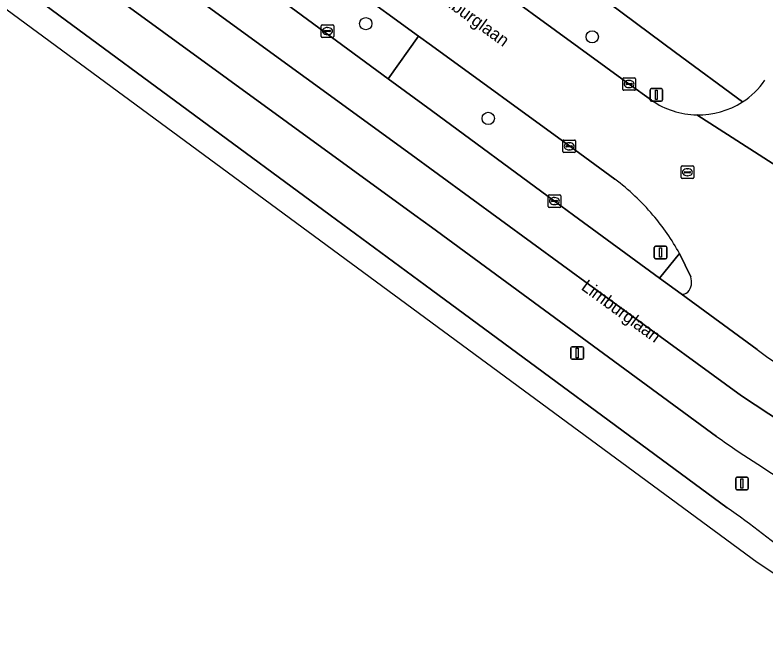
# Model space of a CAD drawing. Extents: x 159674 to 160531, y 382172 to 382904.
# Drawn here: x 159966.8 to 160026.6, y 382215.3 to 382265.9 of the extents above; entities that cross this region are included whole.
import ezdxf

# ---------------------------------------------------------------- set-up
doc = ezdxf.new("R2010")
doc.units = 0
for name, color, linetype in [('IMGEO_Berm_groen', 7, 'Continuous'), ('IMGEO_Boom', 7, 'Continuous'), ('IMGEO_Erf', 7, 'Continuous'), ('IMGEO_Kolk', 7, 'Continuous'), ('IMGEO_Lichtmast', 7, 'Continuous'), ('IMGEO_Openbare_ruimte_label', 7, 'Continuous'), ('IMGEO_Rijbaan_lokaal_open', 7, 'Continuous'), ('IMGEO_Rijbaan_regionaal_gesloten', 7, 'Continuous'), ('IMGEO_Rioolput', 7, 'Continuous'), ('IMGEO_Verkeersbordpaal', 7, 'Continuous'), ('IMGEO_Verkeerseiland_groen', 7, 'Continuous'), ('IMGEO_Verkeerseiland_open', 7, 'Continuous'), ('IMGEO_Voetpad_open', 7, 'Continuous')]:
    doc.layers.add(name, color=color, linetype=linetype)

msp = doc.modelspace()

# ---------------------------------------------------------------- linework, layer by layer
at = {"layer": 'IMGEO_Berm_groen'}
for points in [[(159706.101, 382482.046), (159723.624, 382459.462), (159745.82, 382437.702), (159771.584, 382412.442), (159778.718, 382405.449), (159846.283, 382355.928), (159852.48, 382351.742), (159852.824, 382351.491), (159856.066, 382349.132), (159856.448, 382348.854), (159867.477, 382340.828), (159883.947, 382328.846), (159897.318, 382319.118), (159917.523, 382304.468), (159948.714, 382281.88), (159991.934, 382250), (160000, 382244.05), (160023.542, 382226.685)], [(159820.362, 382389.119), (159843.591, 382372.074), (159859.265, 382360.99), (159859.599, 382360.751), (159862.851, 382358.42), (159863.22, 382358.155), (159864.219, 382357.439), (159890.517, 382338.312), (159899.278, 382331.94), (159949.37, 382295.571), (159996.559, 382260.85), (159998.978, 382264.261), (159993.641, 382268.144), (159978.692, 382279.072), (159964.493, 382289.401), (159948.694, 382300.897), (159932.887, 382312.381), (159917.12, 382323.888), (159901.276, 382335.387), (159892.752, 382341.534), (159890.778, 382342.957), (159886.281, 382346.283)], [(160022.704, 382232.358), (160000, 382249.045), (159998.688, 382250), (159948.547, 382286.492), (159911.807, 382313.056), (159886.027, 382331.843), (159879.684, 382336.466), (159858.583, 382351.787), (159858.205, 382352.061), (159854.963, 382354.415), (159854.637, 382354.652), (159850.158, 382357.904), (159836.086, 382368.415), (159821.924, 382378.682)]]:
    msp.add_lwpolyline(points, dxfattribs=at)
for centre, radius, start, end in [((160091.334, 382330.265), 119.565, 234.97071, 241.71067), ((159975.493, 382158.288), 83.588, 45.29351, 54.91216)]:
    msp.add_arc(centre, radius, start, end, dxfattribs=at)
at = {"layer": 'IMGEO_Boom'}
for centre in [(159994.775, 382265.245), (160012.806, 382264.197), (160004.528, 382257.699)]:
    msp.add_circle(centre, 0.489, dxfattribs=at)
at = {"layer": 'IMGEO_Erf'}
msp.add_lwpolyline([(160086.028, 382319.631), (160083.339, 382319.397), (160078.204, 382311.499), (160083.057, 382302.331), (160067.532, 382294.112), (160051.977, 382285.878), (160036.422, 382277.643), (160020.867, 382269.409), (160016.014, 382278.577), (160005.765, 382273.145), (160019.447, 382262.957), (160024.762, 382259.009)], dxfattribs=at)
msp.add_arc((160021.235, 382264.481), 6.51, 302.80198, 324.89155, dxfattribs=at)
at = {"layer": 'IMGEO_Kolk'}
for p, q in [((159991.223, 382264.23), (159991.223, 382265.082)), ((159991.298, 382265.156), (159992.15, 382265.156)), ((159991.711, 382264.936), (159991.736, 382264.936)), ((159992.224, 382265.082), (159992.224, 382264.23)), ((159991.482, 382264.65), (159991.482, 382264.662)), ((159991.92, 382264.613), (159991.522, 382264.613)), ((159991.525, 382264.699), (159991.923, 382264.699)), ((159991.734, 382264.376), (159991.709, 382264.376)), ((159991.966, 382264.662), (159991.966, 382264.65)), ((159992.15, 382264.156), (159991.298, 382264.156)), ((160015.238, 382260.01), (160015.238, 382260.862)), ((160015.313, 382260.936), (160016.165, 382260.936)), ((160015.726, 382260.716), (160015.751, 382260.716)), ((160016.239, 382260.862), (160016.239, 382260.01)), ((160015.497, 382260.43), (160015.497, 382260.442)), ((160015.935, 382260.393), (160015.537, 382260.393)), ((160015.54, 382260.479), (160015.938, 382260.479)), ((160015.749, 382260.156), (160015.724, 382260.156)), ((160015.981, 382260.442), (160015.981, 382260.43)), ((160016.165, 382259.936), (160015.313, 382259.936)), ((160010.475, 382255.05), (160010.475, 382255.902)), ((160010.55, 382255.976), (160011.402, 382255.976)), ((160011.476, 382255.902), (160011.476, 382255.05)), ((160010.734, 382255.47), (160010.734, 382255.482)), ((160011.172, 382255.433), (160010.774, 382255.433)), ((160010.777, 382255.519), (160011.175, 382255.519)), ((160010.963, 382255.756), (160010.988, 382255.756)), ((160011.218, 382255.482), (160011.218, 382255.47)), ((160011.402, 382254.976), (160010.55, 382254.976)), ((160010.986, 382255.196), (160010.961, 382255.196)), ((160009.294, 382250.687), (160009.294, 382251.539)), ((160009.369, 382251.613), (160010.221, 382251.613)), ((160009.553, 382251.107), (160009.553, 382251.119)), ((160009.991, 382251.07), (160009.593, 382251.07)), ((160009.596, 382251.156), (160009.994, 382251.156)), ((160009.782, 382251.393), (160009.807, 382251.393)), ((160010.037, 382251.119), (160010.037, 382251.107)), ((160010.295, 382251.539), (160010.295, 382250.687)), ((160010.221, 382250.613), (160009.369, 382250.613)), ((160009.805, 382250.833), (160009.78, 382250.833))]:
    msp.add_line(p, q, dxfattribs=at)
for points in [[(159991.223, 382264.23), (159991.223, 382265.082)], [(159991.298, 382265.156), (159992.15, 382265.156)], [(159992.224, 382265.082), (159992.224, 382264.23)], [(159992.15, 382264.156), (159991.298, 382264.156)], [(160015.238, 382260.01), (160015.238, 382260.862)], [(160015.313, 382260.936), (160016.165, 382260.936)], [(160016.239, 382260.862), (160016.239, 382260.01)], [(160016.165, 382259.936), (160015.313, 382259.936)], [(160010.475, 382255.05), (160010.475, 382255.902)], [(160010.55, 382255.976), (160011.402, 382255.976)], [(160011.476, 382255.902), (160011.476, 382255.05)], [(160011.402, 382254.976), (160010.55, 382254.976)], [(160009.294, 382250.687), (160009.294, 382251.539)], [(160009.369, 382251.613), (160010.221, 382251.613)], [(160010.295, 382251.539), (160010.295, 382250.687)], [(160010.221, 382250.613), (160009.369, 382250.613)]]:
    msp.add_lwpolyline(points, dxfattribs=at)
for centre, radius, start, end in [((159991.3, 382265.08), 0.0765, 91.55205, 178.44795), ((159991.3, 382265.08), 0.0765, 91.55205, 178.44795), ((159992.148, 382265.08), 0.0765, 1.55205, 88.44795), ((159992.148, 382265.08), 0.0765, 1.55205, 88.44795), ((159991.3, 382264.232), 0.0765, 181.55205, 268.44795), ((159991.3, 382264.232), 0.0765, 181.55205, 268.44795), ((159991.522, 382264.659), 0.0403, 85.87752, 175.75265), ((159991.519, 382264.649), 0.0366, 178.93798, 274.71019), ((159991.923, 382264.656), 0.043, 264.86636, 352.45326), ((159991.927, 382264.661), 0.0386, 1.73085, 96.63898), ((159992.148, 382264.232), 0.0765, 271.55205, 358.44795), ((159992.148, 382264.232), 0.0765, 271.55205, 358.44795), ((160015.315, 382260.86), 0.0765, 91.55205, 178.44795), ((160015.315, 382260.86), 0.0765, 91.55205, 178.44795), ((160016.163, 382260.86), 0.0765, 1.55205, 88.44795), ((160016.163, 382260.86), 0.0765, 1.55205, 88.44795), ((160015.315, 382260.012), 0.0765, 181.55205, 268.44795), ((160015.315, 382260.012), 0.0765, 181.55205, 268.44795), ((160015.537, 382260.439), 0.0403, 85.87752, 175.75265), ((160015.534, 382260.429), 0.0366, 178.93798, 274.71019), ((160015.938, 382260.436), 0.043, 264.86636, 352.45326), ((160015.942, 382260.441), 0.0386, 1.73085, 96.63898), ((160016.163, 382260.012), 0.0765, 271.55205, 358.44795), ((160016.163, 382260.012), 0.0765, 271.55205, 358.44795), ((160010.552, 382255.9), 0.0765, 91.55205, 178.44795), ((160010.552, 382255.9), 0.0765, 91.55205, 178.44795), ((160011.4, 382255.9), 0.0765, 1.55205, 88.44795), ((160011.4, 382255.9), 0.0765, 1.55205, 88.44795), ((160010.774, 382255.479), 0.0403, 85.87752, 175.75265), ((160010.771, 382255.469), 0.0366, 178.93798, 274.71019), ((160011.175, 382255.476), 0.043, 264.86636, 352.45326), ((160011.179, 382255.481), 0.0386, 1.73085, 96.63898), ((160010.552, 382255.052), 0.0765, 181.55205, 268.44795), ((160010.552, 382255.052), 0.0765, 181.55205, 268.44795), ((160011.4, 382255.052), 0.0765, 271.55205, 358.44795), ((160011.4, 382255.052), 0.0765, 271.55205, 358.44795), ((160009.371, 382251.537), 0.0765, 91.55205, 178.44795), ((160009.371, 382251.537), 0.0765, 91.55205, 178.44795), ((160009.593, 382251.116), 0.0403, 85.87752, 175.75265), ((160009.59, 382251.106), 0.0366, 178.93798, 274.71019), ((160009.994, 382251.113), 0.043, 264.86636, 352.45326), ((160009.998, 382251.118), 0.0386, 1.73085, 96.63898), ((160010.219, 382251.537), 0.0765, 1.55205, 88.44795), ((160010.219, 382251.537), 0.0765, 1.55205, 88.44795), ((160009.371, 382250.689), 0.0765, 181.55205, 268.44795), ((160009.371, 382250.689), 0.0765, 181.55205, 268.44795), ((160010.219, 382250.689), 0.0765, 271.55205, 358.44795), ((160010.219, 382250.689), 0.0765, 271.55205, 358.44795)]:
    msp.add_arc(centre, radius, start, end, dxfattribs=at)
for centre, major_axis, ratio, start_param, end_param in [((159991.71, 382264.656), (-0.387, 0.002), 0.722429, 4.712389, 7.853982), ((159991.735, 382264.656), (-0.39, 0.002), 0.717154, 1.570796, 4.712389), ((160015.725, 382260.436), (-0.387, 0.002), 0.722429, 4.712389, 7.853982), ((160015.75, 382260.436), (-0.39, 0.002), 0.717154, 1.570796, 4.712389), ((160010.962, 382255.476), (-0.387, 0.002), 0.722429, 4.712389, 7.853982), ((160010.987, 382255.476), (-0.39, 0.002), 0.717154, 1.570796, 4.712389), ((160009.781, 382251.113), (-0.387, 0.002), 0.722429, 4.712389, 7.853982), ((160009.806, 382251.113), (-0.39, 0.002), 0.717154, 1.570796, 4.712389)]:
    msp.add_ellipse(centre, major_axis=major_axis, ratio=ratio, start_param=start_param, end_param=end_param, dxfattribs=at)
at = {"layer": 'IMGEO_Lichtmast'}
for p, q in [((160017.515, 382260.067), (160018.305, 382260.067)), ((160018.305, 382260.067), (160017.515, 382260.067)), ((160017.415, 382259.167), (160017.415, 382259.967)), ((160017.415, 382259.967), (160017.415, 382259.167)), ((160018.405, 382259.967), (160018.405, 382259.167)), ((160018.405, 382259.167), (160018.405, 382259.967)), ((160018.305, 382259.067), (160017.515, 382259.067)), ((160017.515, 382259.067), (160018.305, 382259.067)), ((160024.229, 382228.216), (160024.229, 382229.016)), ((160024.229, 382229.016), (160024.229, 382228.216)), ((160024.329, 382229.116), (160025.119, 382229.116)), ((160025.119, 382229.116), (160024.329, 382229.116)), ((160025.219, 382229.016), (160025.219, 382228.216)), ((160025.219, 382228.216), (160025.219, 382229.016)), ((160025.119, 382228.116), (160024.329, 382228.116)), ((160024.329, 382228.116), (160025.119, 382228.116))]:
    msp.add_line(p, q, dxfattribs=at)
for points in [[(160017.835, 382259.942), (160017.985, 382259.942), (160017.985, 382259.192), (160017.835, 382259.192), (160017.835, 382259.942)], [(160024.649, 382228.991), (160024.799, 382228.991), (160024.799, 382228.241), (160024.649, 382228.241), (160024.649, 382228.991)]]:
    msp.add_lwpolyline(points, dxfattribs=at)
for centre, start, end in [((160017.515, 382259.967), 90, 180), ((160017.515, 382259.967), 90, 180), ((160018.305, 382259.967), 0, 90), ((160018.305, 382259.967), 360, 90), ((160017.515, 382259.167), 180, 270), ((160017.515, 382259.167), 180, 270), ((160018.305, 382259.167), 270, 0), ((160018.305, 382259.167), 270, 0), ((160024.329, 382229.016), 90, 180), ((160024.329, 382229.016), 90, 180), ((160025.119, 382229.016), 0, 90), ((160025.119, 382229.016), 360, 90), ((160024.329, 382228.216), 180, 270), ((160024.329, 382228.216), 180, 270), ((160025.119, 382228.216), 270, 0), ((160025.119, 382228.216), 270, 0)]:
    msp.add_arc(centre, 0.1, start, end, dxfattribs=at)
at = {"layer": 'IMGEO_Rijbaan_lokaal_open'}
for points in [[(159821.663, 382393.428), (159837.398, 382381.921), (159853.244, 382370.412), (159861.603, 382364.191), (159861.935, 382363.943), (159862.453, 382363.558), (159865.165, 382361.587), (159865.527, 382361.323), (159868.85, 382358.908), (159886.281, 382346.283), (159890.778, 382342.957), (159892.752, 382341.534), (159901.276, 382335.387), (159917.12, 382323.888), (159932.887, 382312.381), (159948.694, 382300.897), (159964.493, 382289.401), (159978.692, 382279.072), (159993.641, 382268.144), (159998.978, 382264.261), (160000, 382263.517), (160011.011, 382255.498), (160014.603, 382252.861)], [(160017.531, 382259.139), (160015.743, 382260.43), (160000, 382271.92), (159982.528, 382284.68), (159953.332, 382305.907)], [(160021.127, 382257.976), (160029.275, 382252.761)], [(160029.387, 382244.442), (160029.258, 382245.749), (160029.275, 382252.761), (160021.127, 382257.976)], [(160019.751, 382246.941), (160020.65, 382245.079)], [(160019.886, 382243.714), (160025.936, 382239.279)]]:
    msp.add_lwpolyline(points, dxfattribs=at)
for centre, radius, start, end in [((160021.235, 382264.481), 6.51, 302.80198, 324.89155), ((160021.241, 382264.47), 6.495, 235.16301, 268.99303), ((160021.241, 382264.487), 6.512, 268.99679, 302.73155), ((160003.34, 382237.868), 18.753, 40.31369, 53.08594), ((160003.345, 382237.873), 18.745, 28.93175, 40.31233), ((160019.502, 382244.673), 1.217, 318.35143, 19.4825), ((160019.996, 382244.326), 0.622, 259.84321, 311.99003), ((160067.822, 382296.872), 71.213, 233.97243, 247.59079)]:
    msp.add_arc(centre, radius, start, end, dxfattribs=at)
at = {"layer": 'IMGEO_Rijbaan_regionaal_gesloten'}
for points in [[(159778.718, 382405.449), (159782.66, 382401.584), (159867.694, 382338.938), (160025.94, 382222.356), (160036.51, 382215.348)], [(160023.542, 382226.685), (160000, 382244.05), (159991.934, 382250), (159948.714, 382281.88), (159917.523, 382304.468), (159897.318, 382319.118), (159883.947, 382328.846), (159867.477, 382340.828), (159856.448, 382348.854), (159856.066, 382349.132), (159852.824, 382351.491), (159852.48, 382351.742), (159846.283, 382355.928), (159778.718, 382405.449)], [(160025.936, 382239.279), (160019.886, 382243.714), (160018.171, 382244.971), (160011.311, 382250), (160009.795, 382251.111), (160000, 382258.318), (159996.559, 382260.85), (159949.37, 382295.571), (159899.278, 382331.94), (159890.517, 382338.312), (159864.219, 382357.439), (159863.22, 382358.155), (159862.851, 382358.42), (159859.599, 382360.751), (159859.265, 382360.99), (159843.591, 382372.074), (159820.362, 382389.119)], [(159821.924, 382378.682), (159836.086, 382368.415), (159850.158, 382357.904), (159854.637, 382354.652), (159854.963, 382354.415), (159858.205, 382352.061), (159858.583, 382351.787), (159879.684, 382336.466), (159886.027, 382331.843), (159911.807, 382313.056), (159948.547, 382286.492), (159998.688, 382250), (160000, 382249.045), (160022.704, 382232.358)], [(160055.396, 382217.253), (160060.559, 382216.09), (160063.519, 382219.897), (160058.207, 382220.911), (160050.714, 382222.933), (160042.837, 382225.687), (160035.553, 382229.035), (160031.232, 382231.301), (160024.68, 382235.589), (160015.374, 382242.388), (159998.088, 382255.027), (159973.901, 382272.669), (159950.27, 382289.892)], [(159950.27, 382289.892), (159973.901, 382272.669), (159998.088, 382255.027), (160015.374, 382242.388), (160024.68, 382235.589), (160031.232, 382231.301), (160035.553, 382229.035), (160042.837, 382225.687), (160050.714, 382222.933), (160058.207, 382220.911), (160063.519, 382219.897), (160066.547, 382223.791)]]:
    msp.add_lwpolyline(points, dxfattribs=at)
for centre, radius, start, end in [((160067.822, 382296.872), 71.213, 233.97243, 247.59079), ((160091.334, 382330.265), 119.565, 234.97071, 241.71067), ((159975.493, 382158.288), 83.588, 45.29351, 54.91216)]:
    msp.add_arc(centre, radius, start, end, dxfattribs=at)
at = {"layer": 'IMGEO_Rioolput'}
for p, q in [((160019.885, 382252.982), (160019.885, 382253.834)), ((160019.96, 382253.908), (160020.812, 382253.908)), ((160020.187, 382253.451), (160020.585, 382253.451)), ((160020.373, 382253.688), (160020.398, 382253.688)), ((160020.886, 382253.834), (160020.886, 382252.982)), ((160020.812, 382252.908), (160019.96, 382252.908)), ((160020.144, 382253.402), (160020.144, 382253.414)), ((160020.582, 382253.365), (160020.184, 382253.365)), ((160020.396, 382253.128), (160020.371, 382253.128)), ((160020.628, 382253.414), (160020.628, 382253.402))]:
    msp.add_line(p, q, dxfattribs=at)
for points in [[(160019.885, 382252.982), (160019.885, 382253.834)], [(160019.96, 382253.908), (160020.812, 382253.908)], [(160020.886, 382253.834), (160020.886, 382252.982)], [(160020.812, 382252.908), (160019.96, 382252.908)]]:
    msp.add_lwpolyline(points, dxfattribs=at)
for centre, radius, start, end in [((160019.962, 382253.832), 0.0765, 91.55205, 178.44795), ((160019.962, 382253.832), 0.0765, 91.55205, 178.44795), ((160020.184, 382253.411), 0.0403, 85.87752, 175.75265), ((160020.589, 382253.413), 0.0386, 1.73085, 96.63898), ((160020.81, 382253.832), 0.0765, 1.55205, 88.44795), ((160020.81, 382253.832), 0.0765, 1.55205, 88.44795), ((160019.962, 382252.984), 0.0765, 181.55205, 268.44795), ((160019.962, 382252.984), 0.0765, 181.55205, 268.44795), ((160020.181, 382253.401), 0.0366, 178.93798, 274.71019), ((160020.585, 382253.408), 0.043, 264.86636, 352.45326), ((160020.81, 382252.984), 0.0765, 271.55205, 358.44795), ((160020.81, 382252.984), 0.0765, 271.55205, 358.44795)]:
    msp.add_arc(centre, radius, start, end, dxfattribs=at)
for centre, major_axis, ratio, start_param, end_param in [((160020.372, 382253.408), (-0.387, 0.002), 0.722429, 4.712389, 7.853982), ((160020.397, 382253.408), (-0.39, 0.002), 0.717154, 1.570796, 4.712389)]:
    msp.add_ellipse(centre, major_axis=major_axis, ratio=ratio, start_param=start_param, end_param=end_param, dxfattribs=at)
at = {"layer": 'IMGEO_Verkeersbordpaal'}
for p, q in [((160017.848, 382247.515), (160018.638, 382247.515)), ((160018.638, 382247.515), (160017.848, 382247.515)), ((160017.748, 382246.615), (160017.748, 382247.415)), ((160017.748, 382247.415), (160017.748, 382246.615)), ((160018.738, 382247.415), (160018.738, 382246.615)), ((160018.738, 382246.615), (160018.738, 382247.415)), ((160018.638, 382246.515), (160017.848, 382246.515)), ((160017.848, 382246.515), (160018.638, 382246.515)), ((160011.11, 382238.609), (160011.11, 382239.409)), ((160011.11, 382239.409), (160011.11, 382238.609)), ((160011.21, 382239.509), (160012, 382239.509)), ((160012, 382239.509), (160011.21, 382239.509)), ((160012.1, 382239.409), (160012.1, 382238.609)), ((160012.1, 382238.609), (160012.1, 382239.409)), ((160012, 382238.509), (160011.21, 382238.509)), ((160011.21, 382238.509), (160012, 382238.509))]:
    msp.add_line(p, q, dxfattribs=at)
for points in [[(160018.168, 382247.39), (160018.318, 382247.39), (160018.318, 382246.64), (160018.168, 382246.64), (160018.168, 382247.39)], [(160011.53, 382239.384), (160011.68, 382239.384), (160011.68, 382238.634), (160011.53, 382238.634), (160011.53, 382239.384)]]:
    msp.add_lwpolyline(points, dxfattribs=at)
for centre, start, end in [((160017.848, 382247.415), 90, 180), ((160017.848, 382247.415), 90, 180), ((160018.638, 382247.415), 0, 90), ((160018.638, 382247.415), 360, 90), ((160017.848, 382246.615), 180, 270), ((160017.848, 382246.615), 180, 270), ((160018.638, 382246.615), 270, 0), ((160018.638, 382246.615), 270, 0), ((160011.21, 382239.409), 90, 180), ((160011.21, 382239.409), 90, 180), ((160012, 382239.409), 0, 90), ((160012, 382239.409), 360, 90), ((160011.21, 382238.609), 180, 270), ((160011.21, 382238.609), 180, 270), ((160012, 382238.609), 270, 0), ((160012, 382238.609), 270, 0)]:
    msp.add_arc(centre, 0.1, start, end, dxfattribs=at)
at = {"layer": 'IMGEO_Verkeerseiland_groen'}
for points in [[(160011.011, 382255.498), (160000, 382263.517), (159998.978, 382264.261), (159996.559, 382260.85), (160000, 382258.318), (160009.795, 382251.111), (160011.311, 382250), (160018.171, 382244.971), (160019.751, 382246.941)], [(160014.603, 382252.861), (160011.011, 382255.498)]]:
    msp.add_lwpolyline(points, dxfattribs=at)
for centre, radius, start, end in [((160003.34, 382237.868), 18.753, 40.31369, 53.08594), ((160003.345, 382237.873), 18.745, 28.93175, 40.31233)]:
    msp.add_arc(centre, radius, start, end, dxfattribs=at)
at = {"layer": 'IMGEO_Verkeerseiland_open'}
msp.add_lwpolyline([(160020.65, 382245.079), (160019.751, 382246.941), (160018.171, 382244.971), (160019.886, 382243.714)], dxfattribs=at)
for centre, radius, start, end in [((160019.502, 382244.673), 1.217, 318.35143, 19.4825), ((160019.996, 382244.326), 0.622, 259.84321, 311.99003)]:
    msp.add_arc(centre, radius, start, end, dxfattribs=at)
at = {"layer": 'IMGEO_Voetpad_open'}
for points in [[(159887.605, 382353.798), (159890.6, 382351.611), (159893.393, 382349.55), (159896.667, 382347.174), (159905.175, 382340.999), (159920.932, 382329.502), (159937.537, 382317.412), (159953.332, 382305.907), (159982.528, 382284.68), (160000, 382271.92), (160015.743, 382260.43), (160017.531, 382259.139)], [(160024.762, 382259.009), (160019.447, 382262.957), (160005.765, 382273.145), (160003.473, 382274.856), (160000, 382277.384), (159966.979, 382301.422), (159964.599, 382303.191), (159949.672, 382314.284)]]:
    msp.add_lwpolyline(points, dxfattribs=at)
for centre, radius, start, end in [((160021.241, 382264.47), 6.495, 235.16301, 268.99303), ((160021.241, 382264.487), 6.512, 268.99679, 302.73155)]:
    msp.add_arc(centre, radius, start, end, dxfattribs=at)

# ---------------------------------------------------------------- texts
at = {"layer": 'IMGEO_Openbare_ruimte_label'}
for rotation, p in [(324.03584, (159999.778, 382267.683)), (323.90943, (160011.853, 382244.116))]:
    msp.add_text('Limburglaan', height=1, rotation=rotation, dxfattribs=at).set_placement(p)

doc.saveas('drawing.dxf')
